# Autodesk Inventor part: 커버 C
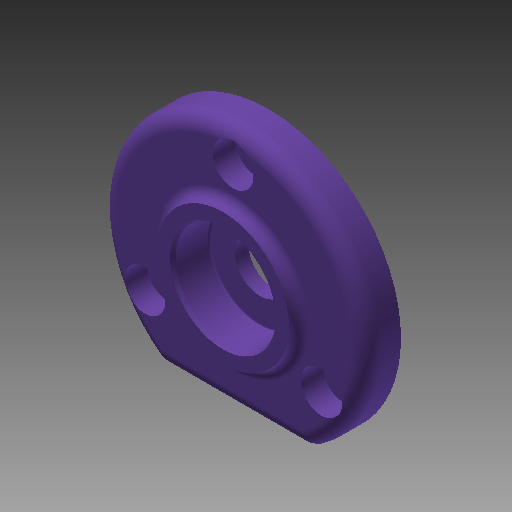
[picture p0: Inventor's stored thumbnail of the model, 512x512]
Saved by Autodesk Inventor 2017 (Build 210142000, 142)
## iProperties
Created: 2020-04
Part Number: 커버 C
Material: 알루미늄 6061
Document SubType Name: Modeling
Designer: mduedu
Density: 1 g/cm^3
Appearance: 보라색
Author: mduedu
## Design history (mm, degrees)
sketch "스케치1"
  geometry: C1 r 26 at (0, 0); 1 further point
  constraints: 1 centre point, 1 coincident
  dimensions: "d0" = 52 diameter of C1
extrude "돌출1" new body sketch "스케치1" distance "d1" = 7; taper "d2" = 0 deg
sketch "스케치2"
  geometry: L1 (-14.62, -21.5)-(14.62, -21.5); A1 r 26 centre (0, 0) between (-14.62, -21.5) and (14.62, -21.5) reference; 1 further point
  constraints: 2 end point, 2 point on circle, 1 horizontal
  dimensions: "d3" = 21.5 distance from line of L1 point (0, 0)
extrude "돌출2" cut sketch "스케치2" stored distance "d4" = 7; taper "d5" = 0 deg
sketch "스케치6"
  geometry: C1 r 13 at (0, 0); 1 further point
  constraints: 1 centre point, 1 coincident
  dimensions: "d29" = 26 diameter of C1
extrude "돌출5" join sketch "스케치6" distance "d30" = 2; taper "d31" = 0 deg
fillet "모깎기1" dims "d6" = 3
fillet "모깎기2" dims "d7" = 3
fillet "모깎기4" dims "d33" = 2
sketch "스케치3" dims "d8" = 40
  geometry: 3 further points
  constraints: 2 vertical alignment, 1 coincident, 2 other
hole "구멍1" sketch "스케치3" at (0, 20) diameter "d9" = 4.5; stored, may be unused: countersink angle "d13" = 90 deg, drill point angle "d15" = 118 deg; dims "d10" = 6, "d11" = 8, "d12" = 4.4, "d14" = 8
sketch "스케치4"
  geometry: C1 r 14 at (0, 0); 1 further point
  constraints: 1 centre point, 1 coincident
  dimensions: "d19" = 28 diameter of C1
extrude "돌출3" join sketch "스케치4" distance "d20" = 4; taper "d21" = 0 deg
sketch "스케치5"
  geometry: C1 r 12 at (0, 0); 1 further point
  constraints: 1 centre point, 1 coincident
  dimensions: "d22" = 24 diameter of C1
extrude "돌출4" cut sketch "스케치5" distance "d23" = 3; taper "d24" = 0 deg
fillet "모깎기3" dims "d25" = 3
chamfer "모따기1" distance "d26" = 0.5; stored, may be unused: second distance "d27" = 2, angle "d28" = 45 deg
sketch "스케치7"
  geometry: 2 further points
  constraints: 1 coincident
hole "구멍2" sketch "스케치7" at (0, 0) diameter "d34" = 10; stored, may be unused: countersink angle "d38" = 90 deg, drill point angle "d40" = 118 deg; dims "d35" = 6, "d36" = 20, "d37" = 7.3, "d39" = 8
fillet "모깎기5" dims "d41" = 0.3
chamfer "모따기2" distance "d42" = 0.7; stored, may be unused: second distance "d43" = 2, angle "d44" = 30 deg
node "솔리드1"
pattern_circular "원형 패턴1" dims angle "d17" = 360 deg
node "투영된 루프1"
